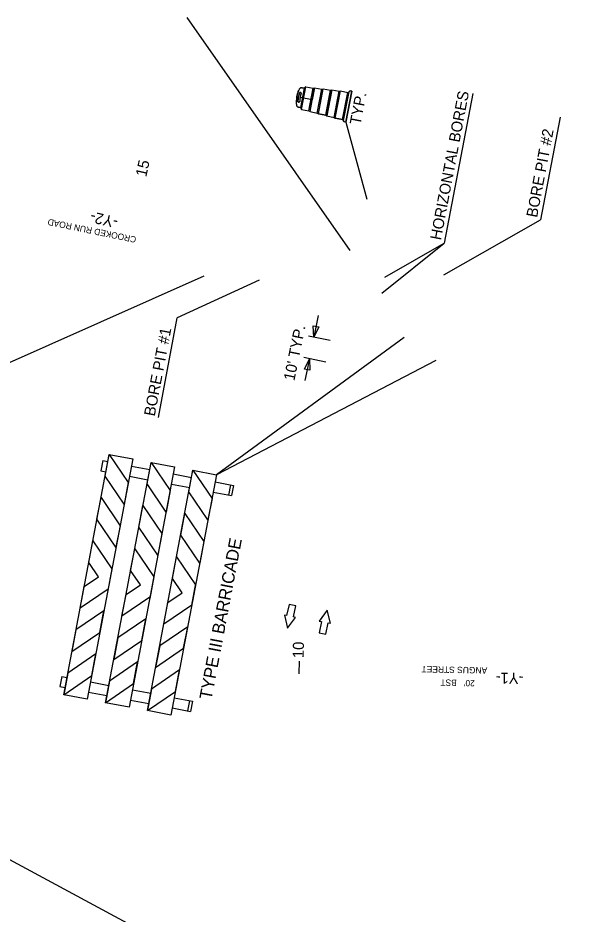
# Model space of a CAD drawing. Extents: x 1615642 to 1617075, y 899305 to 901510.
# Drawn here: x 1616055 to 1616412, y 899679 to 900246 of the extents above; entities that cross this region are included whole.
import ezdxf

# ---------------------------------------------------------------- set-up
doc = ezdxf.new("R2010")
doc.units = 0
for name, color, linetype in [('Default', 7, 'Continuous'), ('DEV DIRECTION OF TRAFFIC FLOW ARROW CELL', 7, 'Continuous'), ('DEV DRUM SECTIONAL VIEW CELL', 7, 'Continuous'), ('DEV TYPE 3 BARRICADE SECTION CELL', 7, 'Continuous'), ('Prop DSN Text', 7, 'Continuous'), ('Prop Horizontal Alignment Tick Label', 7, 'Continuous'), ('Prop Horizontal Alignment Tick Large', 7, 'Continuous'), ('Sheet Clip Boundary CELL', 7, 'Continuous')]:
    doc.layers.add(name, color=color, linetype=linetype)

msp = doc.modelspace()

# ---------------------------------------------------------------- linework, layer by layer
at = {"layer": 'DEV DIRECTION OF TRAFFIC FLOW ARROW CELL'}
for p, q in [((1616226.7, 899874.88), (1616225.18, 899867.85)), ((1616230.95, 899873.96), (1616226.7, 899874.88)), ((1616229.43, 899866.93), (1616230.95, 899873.96)), ((1616250.75, 899871.2), (1616245.71, 899864.27)), ((1616252.88, 899862.9), (1616250.75, 899871.2)), ((1616225.18, 899867.85), (1616223.74, 899868.16)), ((1616223.74, 899868.16), (1616225.66, 899859.81)), ((1616225.66, 899859.81), (1616230.87, 899866.61)), ((1616230.87, 899866.61), (1616229.43, 899866.93)), ((1616245.71, 899864.27), (1616247.16, 899863.99)), ((1616247.16, 899863.99), (1616245.81, 899856.92)), ((1616250.08, 899856.11), (1616251.43, 899863.18)), ((1616251.43, 899863.18), (1616252.88, 899862.9)), ((1616245.81, 899856.92), (1616250.08, 899856.11))]:
    msp.add_line(p, q, dxfattribs=at)
at = {"layer": 'DEV DRUM SECTIONAL VIEW CELL'}
for p, q in [((1616234.09, 900189.17), (1616236.43, 900201.49)), ((1616234.66, 900187.98), (1616237.4, 900202.39)), ((1616236.43, 900201.49), (1616234.99, 900201.76)), ((1616237.4, 900202.39), (1616242.02, 900201.51)), ((1616239.28, 900187.11), (1616242.02, 900201.51)), ((1616239.99, 900186.61), (1616242.85, 900201.71)), ((1616242.02, 900201.51), (1616242.85, 900201.71)), ((1616242.85, 900201.71), (1616247.47, 900200.83)), ((1616244.6, 900185.73), (1616247.47, 900200.83)), ((1616245.31, 900185.24), (1616248.31, 900201.04)), ((1616247.47, 900200.83), (1616248.31, 900201.04)), ((1616248.31, 900201.04), (1616252.92, 900200.16)), ((1616249.93, 900184.36), (1616252.92, 900200.16)), ((1616250.63, 900183.87), (1616253.76, 900200.36)), ((1616252.92, 900200.16), (1616253.76, 900200.36)), ((1616253.76, 900200.36), (1616258.38, 900199.49)), ((1616233.95, 900198.77), (1616233.88, 900198.78)), ((1616255.25, 900182.99), (1616258.38, 900199.49)), ((1616255.95, 900182.5), (1616259.21, 900199.69)), ((1616258.38, 900199.49), (1616259.21, 900199.69)), ((1616259.21, 900199.69), (1616263.83, 900198.81)), ((1616260.57, 900181.62), (1616263.83, 900198.81)), ((1616261.25, 900181.02), (1616264.69, 900199.11)), ((1616262.65, 900179.96), (1616266.37, 900199.59)), ((1616263.83, 900198.81), (1616264.67, 900199.01)), ((1616266.37, 900199.59), (1616265.6, 900199.74)), ((1616234.09, 900189.17), (1616232.65, 900189.45)), ((1616232.78, 900192.61), (1616232.71, 900192.62)), ((1616234.66, 900187.98), (1616239.28, 900187.11)), ((1616239.28, 900187.11), (1616239.99, 900186.61)), ((1616239.99, 900186.61), (1616244.6, 900185.73)), ((1616244.6, 900185.73), (1616245.31, 900185.24)), ((1616245.31, 900185.24), (1616249.93, 900184.36)), ((1616249.93, 900184.36), (1616250.63, 900183.87)), ((1616250.63, 900183.87), (1616255.25, 900182.99)), ((1616255.25, 900182.99), (1616255.95, 900182.5)), ((1616255.95, 900182.5), (1616260.57, 900181.62)), ((1616260.57, 900181.62), (1616261.27, 900181.13)), ((1616262.65, 900179.96), (1616261.88, 900180.11))]:
    msp.add_line(p, q, dxfattribs=at)
for points in [[(1616242.85, 900201.71), (1616241.42, 900194.16), (1616233.72, 900195.62), (1616233.85, 900196.27), (1616233.97, 900196.71), (1616234.06, 900197.09), (1616234.17, 900197.41), (1616234.27, 900197.77), (1616234.37, 900198.05), (1616234.4, 900198.19), (1616234.4, 900198.32), (1616234.34, 900198.48), (1616234.25, 900198.6), (1616234.14, 900198.7), (1616234.03, 900198.76), (1616233.88, 900198.78), (1616233.7, 900198.79), (1616233.54, 900198.73), (1616233.44, 900198.67), (1616233.36, 900198.59), (1616233.3, 900198.52), (1616233.26, 900198.43), (1616233.18, 900198.18), (1616233.1, 900197.92), (1616233.02, 900197.66), (1616232.93, 900197.4), (1616232.85, 900197.06), (1616232.75, 900196.69), (1616232.68, 900196.4), (1616232.63, 900196.15), (1616232.57, 900195.84), (1616231.6, 900196.03), (1616231.69, 900196.48), (1616231.77, 900196.83), (1616231.89, 900197.31), (1616231.98, 900197.64), (1616232.09, 900198.01), (1616232.23, 900198.43), (1616232.4, 900198.9), (1616232.58, 900199.37), (1616232.81, 900199.92), (1616233.02, 900200.38), (1616233.22, 900200.77), (1616233.31, 900200.95), (1616233.41, 900201.12), (1616233.54, 900201.27), (1616233.69, 900201.43), (1616233.84, 900201.53), (1616234.02, 900201.64), (1616234.2, 900201.71), (1616234.4, 900201.76), (1616234.57, 900201.79), (1616234.77, 900201.79), (1616234.92, 900201.77), (1616234.99, 900201.76), (1616236.43, 900201.49), (1616236.62, 900201.75), (1616236.73, 900201.88), (1616236.87, 900202), (1616237.01, 900202.13), (1616237.21, 900202.28), (1616237.32, 900202.34), (1616237.4, 900202.39), (1616242.02, 900201.51)], [(1616244.6, 900185.73), (1616247.47, 900200.83), (1616248.31, 900201.04), (1616252.92, 900200.16), (1616253.76, 900200.36), (1616250.63, 900183.87), (1616249.93, 900184.36), (1616245.31, 900185.24)], [(1616239.99, 900186.61), (1616241.42, 900194.16), (1616233.72, 900195.62), (1616233.65, 900195.25), (1616233.61, 900194.96), (1616233.56, 900194.67), (1616233.53, 900194.36), (1616233.49, 900194.02), (1616233.46, 900193.67), (1616233.44, 900193.29), (1616233.42, 900193.03), (1616233.38, 900192.9), (1616233.3, 900192.79), (1616233.19, 900192.7), (1616233.08, 900192.64), (1616232.97, 900192.61), (1616232.86, 900192.6), (1616232.65, 900192.64), (1616232.54, 900192.69), (1616232.42, 900192.79), (1616232.34, 900192.9), (1616232.28, 900193.06), (1616232.27, 900193.18), (1616232.29, 900193.47), (1616232.31, 900193.85), (1616232.38, 900194.64), (1616232.46, 900195.2), (1616232.53, 900195.62), (1616232.57, 900195.84), (1616231.6, 900196.03), (1616231.52, 900195.63), (1616231.44, 900195.1), (1616231.38, 900194.57), (1616231.33, 900194), (1616231.3, 900193.45), (1616231.28, 900192.86), (1616231.29, 900192.17), (1616231.31, 900191.76), (1616231.36, 900191.1), (1616231.39, 900190.82), (1616231.42, 900190.63), (1616231.48, 900190.43), (1616231.57, 900190.23), (1616231.72, 900190.01), (1616231.88, 900189.84), (1616232.03, 900189.71), (1616232.21, 900189.6), (1616232.4, 900189.51), (1616232.65, 900189.45), (1616234.09, 900189.17), (1616234.12, 900189.02), (1616234.17, 900188.87), (1616234.25, 900188.66), (1616234.36, 900188.45), (1616234.46, 900188.26), (1616234.66, 900187.98), (1616239.28, 900187.11)], [(1616255.25, 900182.99), (1616258.38, 900199.49), (1616259.21, 900199.69), (1616263.83, 900198.81), (1616264.67, 900199.01), (1616264.71, 900199.21), (1616264.76, 900199.32), (1616264.84, 900199.45), (1616264.95, 900199.57), (1616265.04, 900199.64), (1616265.17, 900199.7), (1616265.32, 900199.74), (1616265.43, 900199.75), (1616265.53, 900199.75), (1616265.6, 900199.74), (1616266.37, 900199.59), (1616262.65, 900179.96), (1616261.88, 900180.11), (1616261.77, 900180.14), (1616261.65, 900180.19), (1616261.55, 900180.26), (1616261.46, 900180.33), (1616261.4, 900180.41), (1616261.32, 900180.53), (1616261.27, 900180.67), (1616261.24, 900180.81), (1616261.24, 900180.9), (1616261.25, 900181.02), (1616261.27, 900181.13), (1616260.57, 900181.62), (1616255.95, 900182.5)]]:
    msp.add_lwpolyline(points, close=True, dxfattribs=at)
for centre, radius, start, end in [((1616248.98, 900192.73), 17.69, 152.3001, 186.1986), ((1616234.7, 900200.22), 1.57, 79.2494, 152.3001), ((1616238.7, 900200.01), 2.71, 118.7358, 146.9434), ((1616249.95, 900192.54), 17.69, 160.5754, 177.9234), ((1616233.78, 900198.24), 0.548, 79.2494, 160.5754), ((1616251.1, 900192.32), 17.69, 161.1006, 177.3981), ((1616233.85, 900198.23), 0.548, 341.1006, 79.2494), ((1616265.46, 900198.97), 0.783, 79.2494, 169.2494), ((1616232.95, 900190.99), 1.57, 186.1986, 259.2494), ((1616232.82, 900193.16), 0.548, 177.9234, 259.2494), ((1616232.88, 900193.15), 0.548, 259.2494, 357.3981), ((1616236.75, 900189.72), 2.71, 191.5554, 219.7629), ((1616262.02, 900180.88), 0.783, 169.2494, 259.2494)]:
    msp.add_arc(centre, radius, start, end, dxfattribs=at)
at = {"layer": 'DEV TYPE 3 BARRICADE SECTION CELL'}
for p, q in [((1616083.96, 899817.74), (1616112.82, 899969.77)), ((1616110.22, 899956.09), (1616112.82, 899969.77)), ((1616112.82, 899969.77), (1616127.73, 899966.94)), ((1616112.82, 899969.77), (1616124.9, 899952.03)), ((1616127.73, 899966.94), (1616098.86, 899814.91)), ((1616108.74, 899965.86), (1616107.51, 899959.41)), ((1616108.74, 899965.86), (1616111.96, 899965.25)), ((1616110.48, 899812.7), (1616139.34, 899964.73)), ((1616154.25, 899961.9), (1616125.38, 899809.87)), ((1616126.87, 899962.42), (1616138.48, 899960.21)), ((1616136.74, 899951.05), (1616139.34, 899964.73)), ((1616139.34, 899964.73), (1616154.25, 899961.9)), ((1616139.34, 899964.73), (1616151.42, 899946.99)), ((1616107.51, 899959.41), (1616110.74, 899958.8)), ((1616122.3, 899938.35), (1616110.22, 899956.09)), ((1616137, 899807.67), (1616165.86, 899959.7)), ((1616180.77, 899956.87), (1616151.9, 899804.84)), ((1616153.39, 899957.38), (1616165, 899955.18)), ((1616163.27, 899946.02), (1616165.86, 899959.7)), ((1616165.86, 899959.7), (1616177.94, 899941.96)), ((1616165.86, 899959.7), (1616180.77, 899956.87)), ((1616124.9, 899952.03), (1616122.3, 899938.35)), ((1616125.64, 899955.97), (1616137.26, 899953.76)), ((1616148.82, 899933.32), (1616136.74, 899951.05)), ((1616152.16, 899950.93), (1616163.78, 899948.73)), ((1616179.91, 899952.35), (1616191.53, 899950.14)), ((1616189.59, 899950.51), (1616188.36, 899944.06)), ((1616151.42, 899946.99), (1616148.82, 899933.32)), ((1616175.34, 899928.28), (1616163.27, 899946.02)), ((1616178.69, 899945.9), (1616190.3, 899943.69)), ((1616191.53, 899950.14), (1616190.3, 899943.69)), ((1616105.03, 899928.73), (1616107.63, 899942.41)), ((1616107.63, 899942.41), (1616119.7, 899924.67)), ((1616177.94, 899941.96), (1616175.34, 899928.28)), ((1616131.55, 899923.69), (1616134.15, 899937.37)), ((1616134.15, 899937.37), (1616146.22, 899919.64)), ((1616117.1, 899910.99), (1616105.03, 899928.73)), ((1616158.07, 899918.66), (1616160.67, 899932.34)), ((1616160.67, 899932.34), (1616172.74, 899914.6)), ((1616119.7, 899924.67), (1616117.1, 899910.99)), ((1616143.63, 899905.96), (1616131.55, 899923.69)), ((1616146.22, 899919.64), (1616143.63, 899905.96)), ((1616170.15, 899900.92), (1616158.07, 899918.66)), ((1616099.83, 899901.37), (1616102.43, 899915.05)), ((1616102.43, 899915.05), (1616114.51, 899897.31)), ((1616172.74, 899914.6), (1616170.15, 899900.92)), ((1616126.36, 899896.33), (1616128.95, 899910.01)), ((1616128.95, 899910.01), (1616141.03, 899892.28)), ((1616152.88, 899891.3), (1616155.47, 899904.98)), ((1616155.47, 899904.98), (1616167.55, 899887.24)), ((1616106, 899892.31), (1616099.83, 899901.37)), ((1616114.51, 899897.31), (1616111.91, 899883.63)), ((1616132.52, 899887.27), (1616126.36, 899896.33)), ((1616096.94, 899886.14), (1616106, 899892.31)), ((1616141.03, 899892.28), (1616138.43, 899878.6)), ((1616159.04, 899882.24), (1616152.88, 899891.3)), ((1616165.12, 899874.46), (1616167.72, 899888.14)), ((1616094.35, 899872.46), (1616096.94, 899886.14)), ((1616112.08, 899884.53), (1616094.35, 899872.46)), ((1616123.46, 899881.1), (1616132.52, 899887.27)), ((1616167.55, 899887.24), (1616164.95, 899873.56)), ((1616120.87, 899867.42), (1616123.46, 899881.1)), ((1616138.6, 899879.5), (1616120.87, 899867.42)), ((1616149.98, 899876.07), (1616159.04, 899882.24)), ((1616147.39, 899862.39), (1616149.98, 899876.07)), ((1616165.12, 899874.46), (1616147.39, 899862.39)), ((1616109.48, 899870.86), (1616091.75, 899858.78)), ((1616106.89, 899857.18), (1616109.48, 899870.86)), ((1616136, 899865.82), (1616118.27, 899853.74)), ((1616133.41, 899852.14), (1616136, 899865.82)), ((1616162.53, 899860.78), (1616144.79, 899848.71)), ((1616159.93, 899847.1), (1616162.53, 899860.78)), ((1616091.75, 899858.78), (1616089.15, 899845.1)), ((1616089.15, 899845.1), (1616106.89, 899857.18)), ((1616118.27, 899853.74), (1616115.67, 899840.06)), ((1616115.67, 899840.06), (1616133.41, 899852.14)), ((1616144.79, 899848.71), (1616142.19, 899835.03)), ((1616104.29, 899843.5), (1616086.55, 899831.42)), ((1616101.69, 899829.82), (1616104.29, 899843.5)), ((1616142.19, 899835.03), (1616159.93, 899847.1)), ((1616130.81, 899838.46), (1616113.07, 899826.38)), ((1616128.21, 899824.78), (1616130.81, 899838.46)), ((1616086.55, 899831.42), (1616083.96, 899817.74)), ((1616157.33, 899833.42), (1616139.6, 899821.35)), ((1616154.73, 899819.75), (1616157.33, 899833.42)), ((1616082.81, 899829.32), (1616081.59, 899822.87)), ((1616082.81, 899829.32), (1616086.04, 899828.71)), ((1616083.96, 899817.74), (1616101.69, 899829.82)), ((1616100.94, 899825.88), (1616112.56, 899823.67)), ((1616113.07, 899826.38), (1616110.48, 899812.7)), ((1616081.59, 899822.87), (1616084.81, 899822.26)), ((1616110.48, 899812.7), (1616128.21, 899824.78)), ((1616127.47, 899820.84), (1616139.08, 899818.64)), ((1616139.6, 899821.35), (1616137, 899807.67)), ((1616098.86, 899814.91), (1616083.96, 899817.74)), ((1616099.72, 899819.43), (1616111.33, 899817.22)), ((1616126.24, 899814.39), (1616137.86, 899812.19)), ((1616137, 899807.67), (1616154.73, 899819.75)), ((1616153.99, 899815.81), (1616165.6, 899813.6)), ((1616125.38, 899809.87), (1616110.48, 899812.7)), ((1616152.76, 899809.36), (1616164.38, 899807.15)), ((1616163.67, 899813.97), (1616162.44, 899807.52)), ((1616165.6, 899813.6), (1616164.38, 899807.15)), ((1616151.9, 899804.84), (1616137, 899807.67))]:
    msp.add_line(p, q, dxfattribs=at)
at = {"layer": 'Prop DSN Text'}
for p, q in [((1616161.92, 900246.2), (1616265.14, 900098.7)), ((1616343.01, 900198.05), (1616325.02, 900103.32)), ((1616398.34, 900183.2), (1616385.99, 900118.14)), ((1616262.65, 900179.96), (1616276.06, 900131.31)), ((1616324.71, 900083.37), (1616385.99, 900118.14)), ((1616285.55, 900071.8), (1616325.02, 900103.32)), ((1616287.29, 900081.91), (1616325.02, 900103.32)), ((1615976.93, 899995.57), (1616172.86, 900082.64)), ((1616207.83, 900079.98), (1616155.92, 900056.08)), ((1616143.96, 899993.11), (1616155.92, 900056.08)), ((1616245.15, 900057.62), (1616242.35, 900043.9)), ((1616299.6, 900043.72), (1616180.77, 899956.87)), ((1616252.71, 900041.79), (1616238.92, 900044.6)), ((1616249.94, 900028.18), (1616236.15, 900030.99)), ((1616239.58, 900030.29), (1616236.78, 900016.57)), ((1616319.61, 900029.08), (1616180.77, 899956.87))]:
    msp.add_line(p, q, dxfattribs=at)
for points in [[(1616245.46, 900050.41), (1616242.35, 900043.9), (1616242.04, 900051.11)], [(1616236.47, 900023.78), (1616239.58, 900030.29), (1616239.9, 900023.08)]]:
    msp.add_lwpolyline(points, close=True, dxfattribs=at)
at = {"layer": 'Prop Horizontal Alignment Tick Large'}
msp.add_line((1616233.07, 899830.96), (1616233.23, 899838.95), dxfattribs=at)
at = {"layer": 'Sheet Clip Boundary CELL'}
msp.add_lwpolyline([(1616176.29, 901060.7), (1616913.78, 900900.04), (1616896.28, 900812.91), (1616872.94, 900688.21), (1616835.87, 900695.21), (1616753.94, 900262.18), (1616898.09, 900233.43), (1616663.91, 899565.73), (1616252.62, 899604.04), (1615894.68, 899796.73), (1615981.58, 900932.46), (1616145.94, 900899.57)], close=True, dxfattribs=at)

# ---------------------------------------------------------------- texts
at = {"layer": 'Default'}
for s, rotation, p in [('CROOKED RUN ROAD', 168.458, (1616130.22, 900107.48)), ('ANGUS STREET', 178.7509, (1616352.23, 899835.04)), ("20'   BST", 178.7267, (1616344.42, 899826.98))]:
    msp.add_text(s, height=4, rotation=rotation, dxfattribs=at).set_placement(p)
at = {"layer": 'DEV TYPE 3 BARRICADE SECTION CELL'}
msp.add_text('TYPE III BARRICADE', height=7.8816, rotation=79.2494, dxfattribs=at).set_placement((1616177.56, 899814.16))
at = {"layer": 'Prop DSN Text'}
for s, rotation, p in [('TYP.', 79.2494, (1616271.92, 900177.89)), ('HORIZONTAL BORES', 79.2494, (1616322.9, 900104.98)), ('BORE PIT #2', 79.2494, (1616383.77, 900119.27)), ('BORE PIT #1', 79.2493, (1616141.61, 899993.56)), ("10' TYP.", 78.4796, (1616230.05, 900015.95))]:
    msp.add_text(s, height=7, rotation=rotation, dxfattribs=at).set_placement(p)
at = {"layer": 'Prop Horizontal Alignment Tick Label'}
for s, rotation, p in [('15', 77.7098, (1616136.26, 900144.99)), ('-Y2-', 167.14, (1616118.92, 900119.64)), ('10', 88.5681, (1616235.94, 899840.82)), ('-Y1-', 179.3469, (1616375.22, 899831.55))]:
    msp.add_text(s, height=7, rotation=rotation, dxfattribs=at).set_placement(p)

doc.saveas('drawing.dxf')
